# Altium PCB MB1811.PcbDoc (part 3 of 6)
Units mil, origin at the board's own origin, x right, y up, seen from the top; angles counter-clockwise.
Board outline 3480.3 x 4291.34 mil, 4 copper layers (Top Layer, L2_VCC, L3_GND, Bottom Layer), stack 30.59 mil thick; 371 components, 285 nets, 1369 pads, 606 vias.
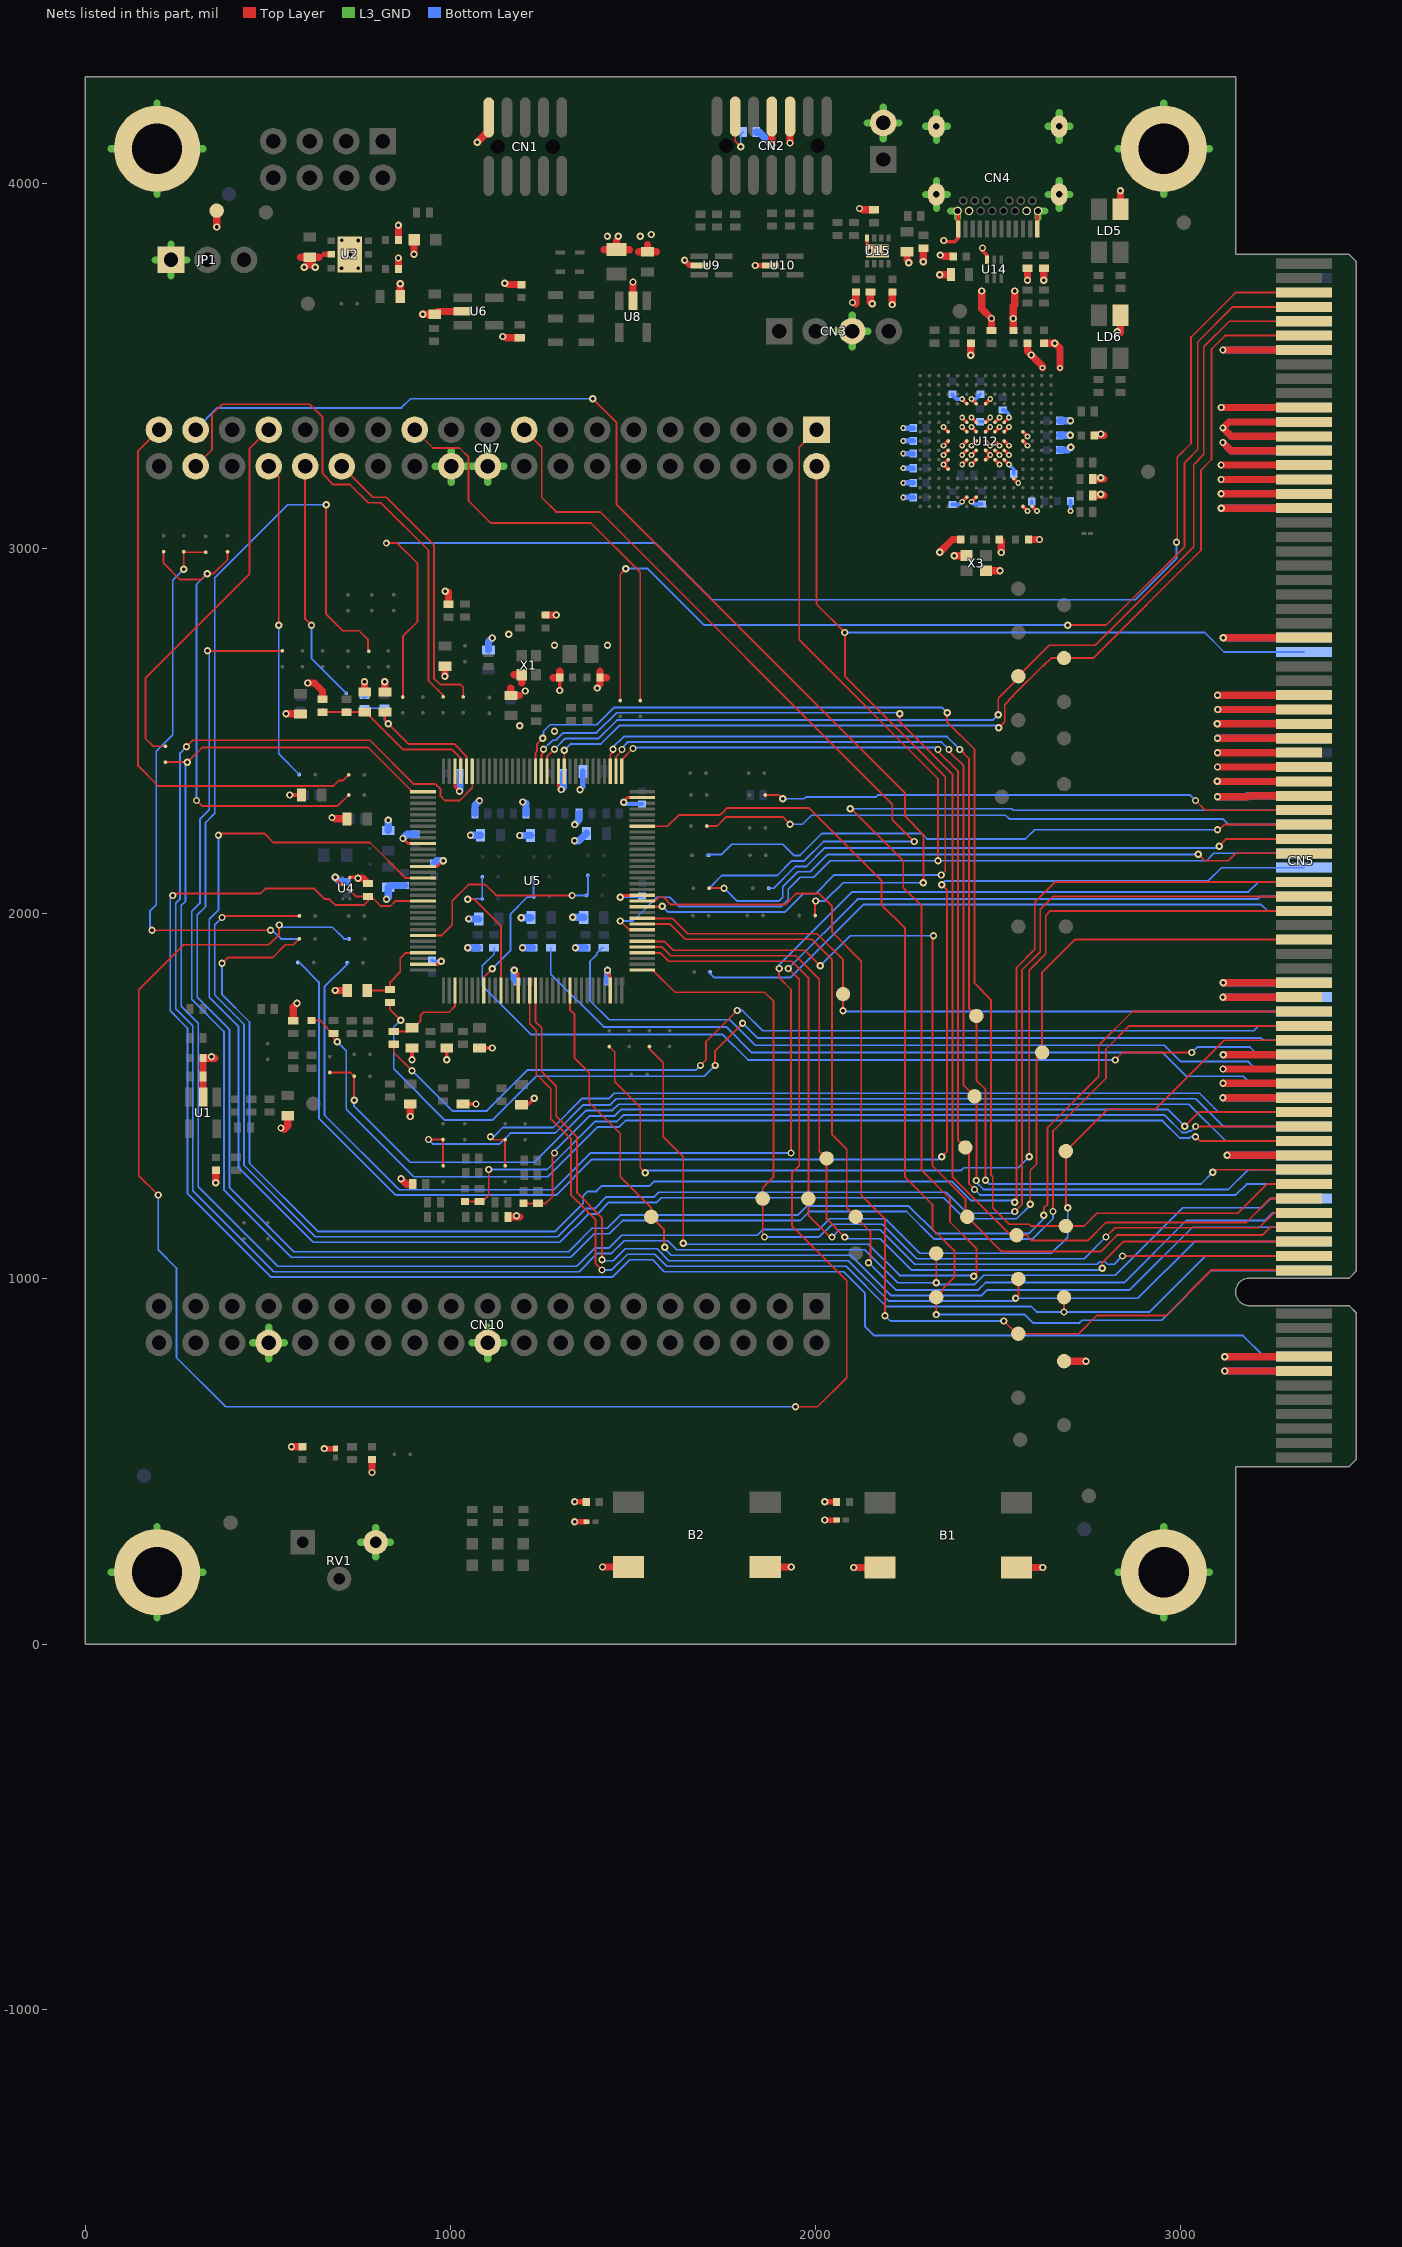
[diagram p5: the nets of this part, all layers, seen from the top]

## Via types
v1: diameter 20, hole 10, Top Layer to Bottom Layer, tented both sides, 524 vias
v2: diameter 16, hole 8, Top Layer to Bottom Layer, tented both sides, 82 vias

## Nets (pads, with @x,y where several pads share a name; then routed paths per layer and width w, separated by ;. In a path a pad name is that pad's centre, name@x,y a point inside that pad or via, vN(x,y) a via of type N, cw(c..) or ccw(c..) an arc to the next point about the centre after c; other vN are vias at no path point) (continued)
GND: B1.1 B1.2 B2.1 B2.2 C2.1 C3.1 C4.1 C5.1 C6.1 C8.1 C9.1 C10.1 C11.1 C12.1 C13.1 C14.1 C15.1 C16.1 C17.1 C18.1 C19.1 C20.1 C21.1 C23.1 C24.1 C25.1 C27.1 C28.1 C29.1 C30.1 C31.1 C32.1 C33.1 C34.2 C35.1 C36.2 C37.1 C38.1 C39.2 C40.2 C41.2 C42.2 C43.1 C44.1 C45.1 C46.1 C47.2 C48.1 C49.2 C50.2 C51.2 C52.2 C53.2 C54.2 C55.2 C56.2 C57.2 C58.2 C59.2 C60.2 C61.2 C62.1 C63.2 C64.1 C65.1 C66.1 C67.1 C68.1 C69.1 C70.1 C71.1 C72.1 C73.1 C74.1 C75.1 C76.1 C77.1 C78.1 C79.1 C80.1 C81.1 C82.1 C83.1 C84.1 C85.1 C86.1 C87.1 CN1.9 CN2.5 CN2.7 CN3.3 CN4.A1 CN4.A12 CN4.B1 CN4.B12 CN4.SH1 CN4.SH2 CN4.SH3 CN4.SH4 CN5.A07 CN5.A20 CN5.A24 CN5.A31 CN5.A32 CN5.A45 CN5.A49 CN5.A56 CN5.A65 CN5.A69 CN5.A76 CN5.B07 CN5.B08 CN5.B20 CN5.B24 CN5.B25 CN5.B26 CN5.B27 CN5.B31 CN5.B32 CN5.B45 CN5.B46 CN5.B47 CN5.B48 CN5.B49 CN5.B50 CN5.B51 CN5.B52 CN5.B56 CN5.B65 CN5.B66 CN5.B67 CN5.B68 CN5.B69 CN5.B70 CN5.B71 CN5.B72 CN5.B76 CN7.20 CN7.22 CN10.20 CN10.32 H1.1 H2.1 H3.1 H4.1 JP1.1 JP3.2 LD4.2 LD5.3 LD6.3 R4.1 R12.1 R34.1 R35.2 R48.2 R49.1 R51.2 R52.2 R56.2 R59.2 R78.1 R80.1 R82.1 R86.2 R87.1 R91.1 R92.1 R93.1 R94.1 R95.1 R96.1 R97.1 R98.1 R99.1 RV1.3 TP1.1 TP32.1 U1.2 U2.2 U2.EP U3.2 U4.2 U4.8 U5.12 U5.30 U5.42 U5.46 U5.63 U5.78 U5.94 U5.110 U5.127 U6.2 U7.2 U8.2 U9.2 U10.2 U11.2 U12.D5 U12.D6 U12.D7 U12.D8 U12.D9 U12.F2 U12.F6 U12.F7 U12.F8 U12.F9 U12.F10 U12.F12 U12.G2 U12.G6 U12.G7 U12.G8 U12.G9 U12.G10 U12.G12 U12.H6 U12.H7 U12.H8 U12.H9 U12.H10 U12.H12 U12.J6 U12.J7 U12.J8 U12.J9 U12.J10 U12.K6 U12.K7 U12.K8 U12.K9 U12.K10 U12.L4 U12.M1 U12.M8 U12.M9 U12.N1 U13.2 U14.3 U15.8 U15.9 X1.2 X3.2 X3.4 | length 19706.8
  Top Layer w8: v1(869.99,2206.04) 883.98,2192.05 U5.42@924.99,2192.05 ; U5.63@924.99,1861.34 966.32,1861.34 v1(974.99,1870.01) ; U5.46@924.99,2129.07 964.81,2129.06 v1(980.76,2145.01) ; U5.30@1012.39,2389.7 1012.39,2347.61 v1(1024.99,2335.01) ; v1(1174.99,1845.01) 1185.62,1834.38 U5.78@1185.62,1789.7 ; U5.12@1295.86,2389.7 1295.85,2349.15 1303.9,2341.1 v1(1303.9,2340.01) ; v1(1429.99,1845.01) 1429.99,1835.86 1437.59,1828.26 U5.94@1437.59,1789.7 ; v1(1464.99,2045.01) 1470.3,2050.32 U5.110@1524.99,2050.33 ; v1(1474.93,2304.76) v1(1474.93,2304.76) 1474.99,2308.03 1484.99,2318.03 U5.127@1524.99,2318.05
  Top Layer w9: v1(684.99,2100.01) 684.99,2095.01 700.15,2079.85 U4.2@705.15,2079.85 ; U15.9@2140.35,3824.22 U15.8@2140.35,3850.13
  Top Layer w10: v1(559.99,2325.01) C5.1@592.43,2325.01 ; U4.8@724.84,2099.54 744.48,2099.54 v1(746.86,2097.16) ; v1(894.99,1600.01) C16.1@894.99,1632.45 ; v1(989.99,1599.85) C20.1@989.99,1632.45 ; C21.1@1034.71,1479.14 v1(1069.99,1479.14) ; C23.1@1079.99,1632.45 v1(1114.99,1632.45) ; C25.1@1194.83,1476.97 1211.95,1476.97 v1(1229.99,1495.01) ; v1(1299,2611) C29.1@1299,2646.29 ; v1(1401.87,2617.7) 1409.44,2625.27 C31.1@1409.44,2646.29 ; U15.9@2140.35,3824.22 v1(2149.87,3814.7) ; v2(2350.02,3255.73) U12.D7@2362.81,3268.52 ; v2@2350.02,3281.33 U12.D8@2362.81,3294.12 ; v2@2350.02,3332.5 U12.D9@2362.81,3319.71 ; v1@2359.87,3839.7 2380.46,3839.7 2390.46,3849.7 2390.46,3922.03 CN4.B1@2388.49,3924 ; U12.D5@2362.81,3217.34 v2(2350.01,3230.14) U12.D6@2362.81,3242.93 ; v2(2401.19,3332.5) U12.F9@2413.99,3319.71 ; v2(2401.19,3358.09) U12.F10@2413.99,3345.3 ; v2(2401.19,3409.27) U12.F12@2413.99,3396.48 ; v2(2401.2,3127.78) U12.F2@2413.99,3140.57 ; v2(2401.2,3230.14) U12.F6@2413.99,3242.93 ; v2(2401.2,3255.73) U12.F7@2413.99,3268.52 ; v2(2401.2,3281.33) U12.F8@2413.99,3294.12 ; v2(2426.79,3127.78) U12.G2@2439.58,3140.57 ; v2(2426.79,3230.14) U12.G6@2439.58,3242.93 ; v2(2426.79,3255.73) U12.G7@2439.58,3268.52 ; v2(2426.79,3281.33) U12.G8@2439.58,3294.12 ; v2(2426.78,3332.5) U12.G9@2439.58,3319.71 ; v2(2426.78,3358.09) U12.G10@2439.58,3345.3 ; v2(2426.78,3409.27) U12.G12@2439.58,3396.48 ; v1(2456.77,3822.7) 2456.77,3815.4 2469.18,3802.99 U14.3@2469.18,3790.29 ; U12.H6@2465.18,3242.93 v2(2477.97,3255.74) U12.H7@2465.18,3268.52 ; U12.H8@2465.18,3294.12 v2(2477.97,3281.33) ; U12.H9@2465.18,3319.71 v2(2477.96,3332.5) ; U12.H10@2465.18,3345.3 v2(2477.96,3358.1) ; U12.H12@2465.18,3396.48 v2(2477.96,3409.27) ; U12.J6@2490.77,3242.93 v2(2503.56,3230.15) ; U12.J7@2490.77,3268.52 v2(2503.55,3255.74) ; U12.J8@2490.77,3294.12 v2(2503.56,3281.33) ; U12.J9@2490.77,3319.71 v2(2503.55,3332.5) ; U12.J10@2490.77,3345.3 v2(2503.55,3358.09) ; U12.K6@2516.36,3242.93 v2(2529.15,3230.15) ; U12.K7@2516.36,3268.52 v2(2529.14,3255.74) ; U12.K8@2516.36,3294.12 v2(2529.14,3281.33) ; U12.K9@2516.36,3319.71 v2(2529.14,3332.5) ; U12.K10@2516.36,3345.3 v2(2529.14,3358.09) ; U12.L4@2541.94,3191.75 v2(2554.73,3178.96) ; U12.M9@2567.54,3319.71 v2(2580.32,3306.92) ; U12.M1@2567.54,3114.98 v2(2580.33,3102.19) ; U12.M8@2567.54,3294.12 v2(2580.33,3281.33) ; U12.N1@2593.13,3114.98 v2(2605.92,3102.19) ; CN4.A1@2607,3874.79 2607,3922.04 CN4.B12@2608.97,3924
  Top Layer w15: v1(654.87,535.62) U3.2@685.27,535.62 ; 654.99,3805.01 U2.2@673.81,3805.01 ; v1(1340,335) U7.2@1372.69,335 ; v1(1340,390) C30.1@1372.27,390 ; v1(1641.17,3788.79) 1643.37,3786.59 1643.37,3786.2 1654.87,3774.7 U9.2@1681.4,3774.7 ; v1(1834.7,3774.7) U10.2@1876.4,3774.7 ; v1(2025,340) U11.2@2057.69,340 ; v1(2025,390) C37.1@2057.27,390
  Top Layer w20: U1.2@322.88,1498.29 322.46,1498.7 322.46,1554.58 R4.1@322.59,1554.7 C86.1@322.59,1604.7 v1@354.87,1604.7 ; v1(357.87,1263.7) C2.1@357.87,1297.27 ; v1(359.99,3880.01) TP1.1@359.99,3925 ; v1@544.87,1409.7 554.87,1419.7 C3.1@554.87,1447.13 ; v1(549.88,2547.14) C24.1@589.87,2547.14 ; v1(564.87,541.04) C6.1@595.27,541.04 ; R78.1@569.87,1707.42 569.87,1744.7 v1(579.87,1754.7) ; 590.45,3797.45 C8.1@614.99,3797.45 ; v1(599.99,3769.85) 614.99,3777.83 ; v1(609.87,2631.68) 627.89,2631.68 649.87,2609.7 R95.1@649.87,2587.42 ; v1(629.99,3769.85) 614.99,3777.83 ; 639.53,3797.45 C8.1@614.99,3797.45 ; v1@684.87,2259.7 C76.1@717.31,2259.7 ; v1(684.99,1790.01) C9.1@717.42,1790.01 ; v1(746.86,2097.16) 760.55,2097.16 R12.1@774.99,2082.72 ; v1(764.87,2634.7) 764.87,2608.04 C10.1@765.66,2607.25 ; v1(785.27,470.29) C11.1@785.27,505.6 ; C13.1@820.66,2607.24 v1(820.66,2635.01) ; C14.1@857.71,3765.01 v1(857.71,3795.01) ; C15.1@857.71,3845.01 v1(857.71,3885.01) ; C12.1@862.55,3690.01 v1(862.55,3725.01) ; v1(864.87,1274.7) 879.87,1259.7 R80.1@897.16,1259.7 ; v1(890,1445.02) C17.1@890,1478.67 ; v1(900.46,3805.48) LD4.2@900.47,3845.01 ; v1(924.59,3641.38) C18.1@957.11,3641.38 964.67,3648.94 U6.2@1033.81,3648.94 ; v1(984.99,2650.03) C19.1@984.99,2677.45 ; R96.1@994.87,2847.42 v1@994.87,2879.7 ; v1(1073.49,4112.11) 1104.99,4143.61 CN1.9@1104.99,4180.12 ; v1@1152.59,3576.98 R34.1@1189.87,3576.98 ; R82.1@1157.59,1169.7 v1@1189.87,1169.7 ; v1@1157.58,3722.41 C27.1@1194.87,3722.41 ; 1164.87,2616.88 1164.87,2597.26 1189.41,2597.26 ; 1174.5,2654.41 X1.2@1195.3,2654.41 1195.3,2631.64 ; C28.1@1259.99,2817.72 v1(1289.99,2817.72) ; 1281.94,2646.29 C29.1@1299,2646.29 1299,2664.34 ; 1409.43,2628.24 C31.1@1409.44,2646.29 ; v1(1416.4,211.42) B2.2@1487.99,211.42 ; 1420.29,3818.16 C32.1@1454.87,3818.16 ; 1426.5,2646.29 C31.1@1409.44,2646.29 ; 1454.87,3842.9 C32.1@1454.87,3818.16 ; 1489.45,3818.16 C32.1@1454.87,3818.16 ; U8.2@1499.88,3678.01 v1(1499.87,3729.7) ; 1515.33,3812.26 C35.1@1539.87,3812.26 ; 1539.87,3831.88 C35.1@1539.87,3812.26 ; 1564.41,3812.26 C35.1@1539.87,3812.26 ; B2.1@1862,211.42 v1(1933.58,211.42) ; v1(1879.99,4105.01) CN2.7@1879.99,4182.6 ; v1(1929.99,4110.01) CN2.5@1929.99,4182.6 ; v1(2104.39,210) B1.2@2175.98,210 ; v1@2109.87,3669.7 C87.1@2109.87,3701.98 ; v1@2129.09,3927.42 R86.2@2159.87,3927.42 ; R87.1@2149.87,3701.98 2149.87,3674.7 v1(2154.87,3669.7) ; v1(2209.87,3667.7) C46.1@2209.87,3701.99 ; C45.1@2249.87,3812.14 2249.87,3789.7 2254.87,3784.7 v1(2254.87,3782.54) ; v1(2294.87,3784.7) R59.2@2294.87,3821.99 ; v1(2339.87,2989.7) 2374.87,3024.7 C39.2@2397.15,3024.7 ; v1(2339.87,3749.7) U13.2@2370.27,3749.7 ; v1@2349.87,3799.7 C42.2@2377.16,3799.7 ; v1(2379.2,2980.37) X3.4@2413.29,2980.37 ; v1(2424.87,3529.13) C33.1@2424.87,3561.99 ; v1(2454.87,3704.7) 2454.87,3656.18 v1(2481.35,3629.7) R48.2@2481.35,3596.84 ; X3.2@2466.44,2939.03 v1(2504.87,2939.03) ; C44.1@2502.59,3024.7 2507.77,3019.51 v1(2507.77,2989) ; C38.1@2541.35,3596.84 v1(2541.35,3629.7) 2541.35,3664 2544.87,3667.52 v1(2544.87,3704.7) ; B1.1@2549.99,210 v1(2621.57,210) ; C34.2@2579.87,3561.98 2579.87,3539.7 v1(2589.87,3529.7) 2620.82,3498.75 v2(2620.82,3494.7) ; v1(2579.87,3734.7) R35.2@2579.87,3766.98 ; C48.1@2582.59,3024.7 v1(2613.07,3024.7) ; C36.2@2624.87,3561.99 v1(2654.87,3561.99) 2669,3547.86 v2(2669,3494) ; v1(2624.87,3734.7) R56.2@2624.87,3766.98 ; TP32.1@2679.99,775 v1(2739.98,775) ; R52.2@2759.07,3145.3 v1@2789.27,3145.3 ; R51.2@2759.07,3190.3 v1@2789.27,3190.3 ; C43.1@2762.59,3309.7 v1@2789.62,3309.7 ; v1@2834.4,3590.17 LD6.3@2834.41,3638.75 ; LD5.3@2834.41,3928.76 v1(2834.4,3979.7) ; v1(3099.67,2519.69) CN5.B50@3336.8,2519.7 ; v1(3099.91,2362.51) 3100.21,2362.21 CN5.B46@3336.8,2362.22 ; v1(3099.99,2320.01) 3184.99,2320.01 3187.82,2322.84 CN5.B45@3336.8,2322.85 ; v1(3099.99,2401.58) CN5.B47@3336.8,2401.59 ; v1(3099.99,2440.95) CN5.B48@3322.82,2440.95 ; v1(3099.99,2480.32) CN5.B49@3336.8,2480.33 ; v1(3099.99,2598.43) CN5.B52@3336.8,2598.44 ; v1(3100.94,2559.06) CN5.B51@3336.8,2559.07 ; v1(3109.99,3149.61) CN5.B66@3336.8,3149.62 ; v1(3109.99,3188.98) CN5.B67@3336.8,3188.99 ; v1(3109.99,3228.35) CN5.B68@3336.8,3228.35 ; v1(3110.22,3110.24) CN5.B65@3336.8,3110.25 ; v1(3110.81,3385.83) CN5.B72@3336.8,3385.84 ; v1(3114.99,1496.07) CN5.B24@3336.8,1496.07 ; v1(3114.99,1771.66) CN5.B31@3322.83,1771.66 ; v1(3114.99,3290.01) 3137.28,3267.72 CN5.B69@3336.8,3267.73 ; v1(3114.99,3543.31) CN5.B76@3336.8,3543.32 ; v1(3115.19,1574.81) CN5.B26@3336.8,1574.81 ; v1(3115.42,1535.44) CN5.B25@3336.8,1535.44 ; v1(3115.82,1614.18) CN5.B27@3336.8,1614.18 ; v1(3115.89,2755.91) CN5.B56@3336.8,2755.92 ; v1(3116.01,1811.03) CN5.B32@3336.8,1811.03 ; v1(3119.99,748.04) CN5.B07@3336.8,748.04 ; v1(3119.99,787.41) CN5.B08@3336.8,787.41 ; v1(3126.41,1338.59) CN5.B20@3336.8,1338.59 ; CN5.B70@3336.8,3307.1 3137.91,3307.09 v1(3114.99,3330.01) 3131.44,3346.46 CN5.B71@3336.8,3346.47 ; 614.99,3777.83 C8.1@614.99,3797.45 ; C31.1@1409.44,2646.29 1409.44,2664.34 C31.1@1409.44,2646.29
  L3_GND w20: 71.7,196.87 H3.1@196.84,196.86 ; 71.7,4094.5 H4.1@196.84,4094.49 ; 191.54,3790.01 JP1.1@234.99,3790 ; 196.83,71.74 H3.1@196.84,196.86 ; 196.83,322 H3.1@196.84,196.86 ; 196.83,3969.37 H4.1@196.84,4094.49 ; 196.83,4219.63 H4.1@196.84,4094.49 ; 234.98,3746.57 JP1.1@234.99,3790 ; 234.98,3833.45 JP1.1@234.99,3790 ; 278.42,3790.01 JP1.1@234.99,3790 ; 321.96,196.87 H3.1@196.84,196.86 ; 321.96,4094.5 H4.1@196.84,4094.49 ; 458.92,825.01 CN10.32@502.37,825 ; 502.36,781.57 CN10.32@502.37,825 ; 502.36,868.45 CN10.32@502.37,825 ; 545.8,825.01 CN10.32@502.37,825 ; 754.77,279.12 RV1.3@795.27,279.11 ; 795.26,238.63 RV1.3@795.27,279.11 ; 795.26,319.61 RV1.3@795.27,279.11 ; 835.75,279.12 RV1.3@795.27,279.11 ; 958.92,3225.01 CN7.22@1002.37,3225 ; 1002.36,3181.57 CN7.22@1002.37,3225 ; 1002.36,3268.45 CN7.22@1002.37,3225 ; 1045.8,3225.01 CN7.22@1002.37,3225 ; 1058.92,825.01 CN10.20@1102.37,825 ; 1058.92,3225.01 CN7.20@1102.37,3225 ; 1102.36,781.57 CN10.20@1102.37,825 ; 1102.36,868.45 CN10.20@1102.37,825 ; 1102.36,3181.57 CN7.20@1102.37,3225 ; 1102.36,3268.45 CN7.20@1102.37,3225 ; 1145.8,825.01 CN10.20@1102.37,825 ; 1145.8,3225.01 CN7.20@1102.37,3225 ; 2056.54,3595.01 CN3.3@2099.99,3595 ; 2099.98,3551.57 CN3.3@2099.99,3595 ; 2099.98,3638.45 CN3.3@2099.99,3595 ; 2141.54,4165.02 JP3.2@2184.99,4165.01 ; 2143.42,3595.01 CN3.3@2099.99,3595 ; 2184.98,4121.58 JP3.2@2184.99,4165.01 ; 2184.98,4208.46 JP3.2@2184.99,4165.01 ; 2228.42,4165.02 JP3.2@2184.99,4165.01 ; 2300.95,3969.29 CN4.SH3@2330.61,3969.29 ; 2300.95,4155.51 CN4.SH4@2330.61,4155.51 ; 2330.61,3931.76 CN4.SH3@2330.61,3969.29 ; 2330.61,4006.82 CN4.SH3@2330.61,3969.29 ; 2330.61,4117.98 CN4.SH4@2330.61,4155.51 ; 2330.61,4193.04 CN4.SH4@2330.61,4155.51 ; 2360.27,3969.29 CN4.SH3@2330.61,3969.29 ; 2360.27,4155.51 CN4.SH4@2330.61,4155.51 ; 2369.65,3924.02 CN4.B1@2388.49,3924 2388.48,3905.19 ; 2608.95,3905.19 CN4.B12@2608.97,3924 2627.78,3924.02 ; 2637.17,3969.29 CN4.SH1@2666.84,3969.28 ; 2637.17,4155.51 CN4.SH2@2666.84,4155.5 ; 2666.83,3931.76 CN4.SH1@2666.84,3969.28 ; 2666.83,4006.82 CN4.SH1@2666.84,3969.28 ; 2666.83,4117.98 CN4.SH2@2666.84,4155.5 ; 2666.83,4193.04 CN4.SH2@2666.84,4155.5 ; 2696.49,3969.29 CN4.SH1@2666.84,3969.28 ; 2696.49,4155.51 CN4.SH2@2666.84,4155.5 ; 2827.6,196.87 H1.1@2952.74,196.86 ; 2827.6,4094.5 H2.1@2952.74,4094.49 ; 2952.73,71.74 H1.1@2952.74,196.86 ; 2952.73,322 H1.1@2952.74,196.86 ; 2952.73,3969.37 H2.1@2952.74,4094.49 ; 2952.73,4219.63 H2.1@2952.74,4094.49 ; 3077.86,196.87 H1.1@2952.74,196.86 ; 3077.86,4094.5 H2.1@2952.74,4094.49
  Bottom Layer w10: C79.1@949.99,1872.73 952.71,1870.01 v1(974.99,1870.01) ; v1(1464.99,2045.01) 1468.33,2048.35 C64.1@1524.99,2048.35 ; v1(1474.93,2304.76) 1479.37,2300.32 C65.1@1524.99,2300.32 ; C50.2@2374.7,3120.4 2375.7,3121.4 2379.7,3121.4 2394.82,3121.4 v2(2401.2,3127.78) ; C62.1@2374.87,3421.99 2374.87,3419.27 2384.87,3409.27 v2(2401.19,3409.27) ; v2(2426.79,3127.78) 2432.69,3121.88 C51.2@2455.18,3121.88 ; v2(2426.78,3409.27) 2438.16,3409.27 C40.2@2450.87,3421.98 ; C63.2@2449.87,3346.98 2466.84,3346.98 v2(2477.96,3358.1) ; C41.2@2512.27,3378.88 2517.97,3378.88 2529.14,3367.71 v2(2529.14,3358.09) ; v2(2529.15,3230.15) 2542.42,3216.86 C54.2@2542.42,3204.12 ; v2(2529.15,3230.15) 2542.42,3216.88 ; v2@2554.73,3176.85 v2(2554.73,3178.96) ; C52.2@2591.99,3129.12 2591.98,3116.12 v2@2605.91,3102.19
  Bottom Layer w12: v2(2697.59,3102.42) C47.2@2697.6,3129.7
  Bottom Layer w15: v1(1354.99,2339.65) 1354.99,2340.01 1362.78,2347.8 C69.1@1362.78,2389.69 ; v2(2239.87,3139.7) C49.2@2267.16,3139.7 ; v2(2239.87,3179.58) C53.2@2267.48,3179.58 ; v2(2239.87,3219.58) C55.2@2267.48,3219.58 ; v2(2239.87,3259.58) C56.2@2267.48,3259.58 ; v2(2239.87,3294.58) C58.2@2267.48,3294.58 ; v2(2239.87,3329.7) C60.2@2267.16,3329.7
  Bottom Layer w20: v1(684.99,2100.01) 697.28,2087.72 C85.1@714.99,2087.72 ; R94.1@764.87,2597.42 v1(764.87,2634.7) ; v1(824.99,2040.01) 829.99,2045.01 829.99,2072.45 834.84,2077.3 C82.1@874.99,2077.3 ; v1(829.72,2256.36) 829.72,2227.84 C84.1@829.99,2227.57 ; v1(869.99,2206.04) 881.67,2217.72 C81.1@904.99,2217.72 ; C78.1@954.99,2137.73 962.27,2145.01 v1(980.76,2145.01) ; v1(1024.99,2335.01) 1026.17,2336.19 C77.1@1026.18,2384.69 ; v1(1047.27,1906.97) R93.1@1074.87,1906.98 ; v1@1049.84,1985.76 C75.1@1077.43,1985.76 ; v1(1054.87,2215.01) C74.1@1082.43,2215.01 ; R99.1@1067.16,2274.7 1067.15,2296.98 v1(1079.87,2309.7) ; C4.1@1104.56,2722.14 1104.56,2744.39 v1(1114.87,2754.7) ; v1(1174.99,1845.01) 1174.99,1822.29 C73.1@1182.27,1815.01 ; v1(1189.87,2214.11) C72.1@1219.68,2214.11 ; v1(1194.25,1989.27) C71.1@1220.89,1989.28 ; v1(1197.27,1906.97) R91.1@1224.87,1906.98 ; R97.1@1207.16,2274.7 v1@1207.15,2302.42 ; v1(1303.9,2340.01) 1309.63,2345.74 C70.1@1309.64,2384.69 ; v1(1334.98,1990) C68.1@1364.99,1990 ; v1(1339.87,2199.7) 1352.13,2199.7 C67.1@1372.43,2220 ; v1(1340.19,2244.02) 1340.19,2244.38 1352.15,2256.34 R98.1@1352.16,2274.7 ; v1(1342.27,1906.97) R92.1@1369.87,1906.98 ; v1(1429.99,1845.01) 1429.99,1817.3 C66.1@1432.28,1815.01 ; R49.1@1837.59,4139.7 1845.3,4139.7 v1(1879.99,4105.01) ; C57.2@2667.9,3269.58 2690.75,3269.58 v1(2698.37,3277.2) ; C59.2@2667.9,3309.58 v1(2697.11,3309.58) ; C61.2@2667.9,3349.58 v1(2697.93,3349.58) ; v1(3099.99,2320.01) 3179.99,2320.01 3182.82,2322.84 CN5.A45@3336.8,2322.85 ; v1(3099.99,2480.32) CN5.A49@3336.8,2480.33 ; v1(3110.22,3110.24) CN5.A65@3336.8,3110.25 ; v1(3114.99,1496.07) CN5.A24@3336.8,1496.07 ; v1(3114.99,1771.66) CN5.A31@3336.8,1771.66 ; v1(3114.99,3290.01) 3137.28,3267.72 CN5.A69@3336.8,3267.73 ; v1(3114.99,3543.31) CN5.A76@3336.8,3543.32 ; v1(3115.89,2755.91) CN5.A56@3336.8,2755.92 ; v1(3116.01,1811.03) CN5.A32@3336.8,1811.03 ; v1(3119.99,748.04) CN5.A07@3336.8,748.04 ; v1(3126.41,1338.59) CN5.A20@3336.8,1338.59
  other v1: 1181.03,1173.21 536.03,1413.21 346.03,1608.21 1049.83,1985.75 676.03,2263.21 1198.31,2305.93 1284.87,2499.7 1189.87,2514.45 1204.87,2609.7 1284.99,2735.01 1429.99,2735.01 1159.99,2765.01 986.03,2883.21 2780.43,3148.81 2780.43,3193.81 2780.78,3313.21 1143.75,3580.49 2825.56,3593.68 2101.03,3673.21 1148.74,3725.92 701.99,3767.01 747.99,3767.01 2341.03,3803.21 724.99,3805.01 2189.87,3814.7 747.99,3843.01 702.99,3844.01 2351.03,3843.21 1429.87,3854.7 1459.87,3854.7 1519.87,3854.7 1549.87,3859.7 2120.25,3930.93
  other v2: 2350.01,3281.33 2350.01,3332.5
GNDDetect: CN2.11 R49.2 | length 132.7
  Top Layer w5: CN2.11@1779.99,4182.6 1779.99,4115.01 v1(1794.99,4100.01)
  Bottom Layer w5: v1(1794.99,4100.01) 1794.99,4134.7 1799.99,4139.7 R49.2@1802.15,4139.7
ID_Enable: CN5.A08 R12.2 U4.6 U5.52 | length 4972.5
  Top Layer w5: v1(239.87,2049.7) 245.87,2055.7 480.87,2055.7 493.87,2068.7 627.86,2068.7 656.55,2040.01 668.56,2040.01 679.49,2029.08 685.44,2023.98 763.96,2023.98 774.99,2035.01 R12.2@774.99,2047.29 ; U4.6@724.84,2060.17 728.48,2060.17 741.36,2047.29 R12.2@774.99,2047.29 ; U5.52@924.99,2034.58 849.54,2034.57 836.07,2021.1 808.9,2021.1 782.71,2047.29 R12.2@774.99,2047.29
  Bottom Layer w5: v1(239.87,2049.7) 232.99,2042.82 232.99,1734.02 279.87,1687.14 279.87,1235.13 509.99,1005.01 1443.52,1005.01 1491.05,1052.51 1553.46,1052.51 1585.96,1020.01 2077.01,1020.01 2134.99,962.03 2134.99,870.01 2159.99,845.01 3169.99,845.01 3227.59,787.41 CN5.A08@3336.8,787.41
Inrush_lim.: CN5.B35 TP30.1 U5.48 | length 5313.3
  Top Layer w5: v1(364.87,2214.7) 370.18,2220.01 489.98,2220.01 514.98,2195.01 779.99,2195.01 877.44,2097.56 U5.48@924.99,2097.57 ; v1(2587.37,1204.7) 2587.37,1297.2 2604.87,1314.7 2604.87,1604.89 TP30.1@2619.99,1620.01 2619.99,1839.81 2709.32,1929.14 CN5.B35@3336.8,1929.14
  Bottom Layer w5: v1(364.87,2214.7) 364.87,2009.7 339.87,1984.7 339.87,1771.25 419.99,1691.13 419.99,1304.7 624.28,1100.41 1299.79,1100.41 1377.08,1177.7 1401.52,1177.7 1433.52,1209.7 1564.5,1209.7 1577,1222.2 2351.16,1222.2 2408.66,1164.7 2549.88,1164.7 2587.37,1202.19 v1(2587.37,1204.7)
L1_PG6: CN5.A41 CN7.1 U5.104 | length 3413.2
  Top Layer w5: v1(1464.99,1980.01) 1489.17,1955.83 U5.104@1524.99,1955.84 ; CN7.1@2002.37,3325 1954.99,3277.62 1954.99,2750.01 2334.87,2370.13 v1(2334.87,2145.01)
  Bottom Layer w5: v1(1464.99,1980.01) 1499.99,1980.01 1564.99,2045.01 1599.99,2045.01 1624.99,2020.01 1906.4,2020.01 1924.87,2038.48 1924.87,2067.25 1957.32,2099.7 1994.87,2099.7 2040.18,2145.01 v1(2334.87,2145.01) 3069.99,2145.01 3090.34,2165.36 CN5.A41@3336.8,2165.36
L2_PD0: CN5.A55 CN7.2 U5.108 | length 3416.1
  Top Layer w5: U5.108@1524.99,2018.83 1563.8,2018.82 1564.55,2019.57 1578.99,2019.57 v1(1579.99,2020.57) ; CN7.2@2002.37,3225 2002.35,2847.66 v1(2079.99,2770.01) 2079.99,2650.01 2354.87,2375.13 2354.87,2117.51 v1(2343.47,2106.11)
  Bottom Layer w5: v1(1579.99,2020.57) 1595.55,2005.01 1916.21,2005.01 1965.9,2054.7 1999.86,2054.7 2051.27,2106.11 v1(2343.47,2106.11) ; v1(2079.99,2770.01) 3064.55,2770.01 3118.02,2716.54 CN5.A55@3336.8,2716.55
L17_PD3: CN7.17 SB70.2 | length 2254
  Top Layer w5: CN7.17@1202.37,3325 1249.99,3277.38 1249.99,3139.57 1289.55,3100.01 1409.57,3100.01 2209.87,2299.71 2209.87,2257.51 v1(2269.87,2197.51)
  Bottom Layer w5: SB70.2@1708.61,2070.01 1743.3,2104.7 1894.68,2104.7 1934.68,2144.7 1968.65,2144.7 2021.46,2197.51 v1(2269.87,2197.51)
L23_PE5: CN7.23 SB44.2 | length 1200.6
  Top Layer w5: CN7.23@902.37,3325 952.36,3275.01 1024.99,3275.01 1049.99,3250.01 1049.99,3130.01 1110.3,3069.7 1384.86,3069.7 1519.99,2934.57 SB44.2@1519.99,2583.63
L28_PC2: CN7.28 SB34.2 | length 823.4
  Top Layer w5: CN7.28@702.37,3225 787.36,3140.01 824.56,3140.01 954.99,3009.58 954.99,2644.57 972.05,2627.51 1027.49,2627.51 1034.99,2620.01 SB34.2@1034.99,2593.64
L30_PA3: CN7.30 SB82.2 | length 668.3
  Top Layer w5: CN7.30@602.37,3225 602.37,2807.2 v1(619.87,2789.7)
  Bottom Layer w5: v1(619.87,2789.7) 619.87,2698.32 SB82.2@714.87,2603.32
L31_PA4: CN7.31 SB61.2 | length 1049
  Top Layer w5: SB61.2@219.87,2458.32 186.25,2458.32 164.87,2479.7 164.87,2644.7 449.87,2929.7 449.87,3272.5 CN7.31@502.37,3325
L32_PA5: CN7.32 SB91.2 | length 878.7
  Top Layer w5: CN7.32@502.37,3225 529.87,3197.5 v1(529.87,2789.7)
  Bottom Layer w5: v1(529.87,2789.7) 529.87,2437.55 SB91.2@586.37,2381.06
L34_PE10: SB62.2 SB64.2 SB90.2 | length 1551.4
  Top Layer w5: v1(182.99,1954.7) 507.18,1954.7 v1(507.49,1955.01) ; v1(270,2943) 269.87,2943.13 SB64.2@269.87,2991.15 271.32,2989.69 SB62.2@330,2989.69
  Bottom Layer w5: v1(182.99,1954.7) 182.99,1956.58 177.37,1962.2 177.37,2007.2 194.87,2024.7 194.87,2444.7 239.87,2489.7 239.87,2912.87 v1(270,2943) ; v1(507.49,1955.01) 512.49,1955.01 536.43,1931.07 SB90.2@586.37,1931.07
L35_PA9: CN7.35 SB60.2 | length 3178.5
  Top Layer w5: v1(1389.87,3409.7) 1454.87,3344.7 1454.87,3119.7 2244.87,2329.7 2244.87,2266.69 2294.99,2216.57 v1(2294.99,2085.01) ; SB60.2@1998.61,1995.01 1998.61,2033.63 v1(1999.99,2035.01)
  Bottom Layer w5: CN7.35@302.37,3325 362.07,3384.7 865.87,3384.7 890.87,3409.7 v1(1389.87,3409.7) ; v1(1999.99,2035.01) 2025.19,2035.01 2075.19,2085.01 v1(2294.99,2085.01)
L36_PC3: CN7.36 SB30.2 | length 1441.4
  Top Layer w5: CN7.36@302.37,3225 347.38,3270.01 347.38,3367.21 374.87,3394.7 614.87,3394.7 649.99,3359.58 649.99,3204.57 679.86,3174.7 725.18,3174.7 774.87,3125.01 809.56,3125.01 939.99,2994.58 939.99,2638.35 965.83,2612.51 ; 967.07,2612.51 965.83,2612.51 ; SB30.2@980,2593.62 SB30.2@979.99,2598.35 ; 979.99,2599.59 SB30.2@979.99,2598.35 ; 965.83,2612.51 SB30.2@979.99,2598.35
L37_PA7: CN7.37 SB17.2 | length 1555.7
  Top Layer w5: CN7.37@202.37,3325 144.87,3267.5 144.87,2404.69 199.55,2350.01 576.7,2350.01 ; 576.72,2350.03 663.26,2350.03 ; 663.28,2350.01 679.99,2350.01 694.99,2365.01 706.37,2365.01 SB17.2@721.38,2380.01
L38_PC4: SB15.2 SB63.2 SB65.2 | length 1337.3
  Top Layer w5: SB65.2@214.87,2991.16 214.87,2959.7 259.57,2915 318,2915 v1(334,2931) 351.17,2931 389.87,2969.7 SB63.2@389.87,2991.16 ; v1(304.87,2310.01) 319.87,2295.01 691.37,2295.01 SB15.2@721.37,2325.01
  Bottom Layer w5: v1(304.87,2310.01) 304.87,2901.87 v1(334,2931)
M1_DissipativeBrake: CN5.A30 TP9.1 U5.106 | length 1998.9
  Top Layer w5: U5.106@1524.99,1987.34 1525.48,1986.83 1607.85,1986.83 1611.1,1983.58 1611.18,1983.58 1649.75,1945.01 2003.77,1945.01 2074.99,1873.79 TP9.1@2074.99,1780.01 v1(2074.99,1734.7)
  Bottom Layer w5: v1(2074.99,1734.7) 2077.39,1732.3 CN5.A30@3336.8,1732.29
M1_Emergency(BKIN2): CN5.B12 TP21.1 U5.109 | length 2980.4
  Top Layer w5: U5.109@1524.99,2034.58 1559.55,2034.57 1569.99,2045.01 1583.77,2045.01 1603.77,2025.01 1916.21,2025.01 1946.21,2055.01 2009.99,2055.01 2044.99,2020.01 2044.99,1950.01 2124.99,1870.01 2124.99,1229.02 2189.99,1164.02 v1(2189.99,899.7) ; v1(2514.99,885.01) 2550,850 TP21.1@2554.99,850 2719.98,850 2769.99,900.01 2960,900.01 3084.99,1025 3335.43,1025 CN5.B12@3336.8,1023.63
  Bottom Layer w5: v1(2189.99,899.7) 2204.68,885.01 v1(2514.99,885.01)
M1_Emergency(BKIN): CN5.A12 TP12.1 U5.122 | length 3126.3
  Top Layer w5: U5.122@1524.99,2239.31 1594.27,2239.29 1624.99,2270.01 1737.43,2270.01 1742.43,2275.01 1743.77,2275.01 1758.46,2289.7 1981.52,2289.7 2179.99,2091.23 2179.99,2025.01 2244.99,1960.01 2244.99,1278.78 2319.99,1203.78 2319.99,1137.57 2379.99,1077.57 2379.99,1005 2349.23,974.24 2349.23,969.25 TP12.1@2329.99,950.01 v1(2329.99,902.51)
  Bottom Layer w5: v1(2329.99,902.51) 2572.06,902.51 2594.87,879.7 2722.07,879.7 2729.57,887.2 2947.18,887.2 3083.61,1023.63 CN5.A12@3336.8,1023.63
M1_Enable1: CN5.B77 TP37.1 U5.11 | length 2892.7
  Top Layer w5: U5.11@1311.6,2389.7 v1(1311.6,2447.51) ; v1(2501.24,2508.76) 2517.49,2525.01 2517.49,2572.51 2539.99,2595.01 2539.99,2596.23 2623.77,2680.01 2624.99,2680.01 2644.99,2700.01 TP37.1@2679.99,2700.01 2759.99,2700.01 3054.99,2995.01 3054.99,3214.7 3083.77,3243.48 3083.77,3545.79 3120.66,3582.68 CN5.B77@3336.8,3582.69
  Bottom Layer w5: v1(1311.6,2447.51) 1329.1,2465.01 1412.31,2465.01 1462.31,2515.01 2494.99,2515.01 v1(2501.24,2508.76)
M1_Enable2: CN5.B78 TP26.1 U5.14 | length 2939.5
  Top Layer w5: U5.14@1264.36,2389.7 1264.36,2429.38 v1(1284.99,2450.01) ; v1(2499.99,2545.01) 2499.99,2590.01 2554.99,2645.01 TP26.1@2554.99,2650.01 2639.99,2735.01 2764.99,2735.01 3034.99,3005.01 3034.99,3229.7 3062.77,3257.48 3062.77,3551.79 3133.03,3622.05 CN5.B78@3336.8,3622.05
  Bottom Layer w5: v1(1284.99,2450.01) 1314.99,2480.01 1406.09,2480.01 1456.09,2530.01 2484.99,2530.01 v1(2499.99,2545.01)
M1_Encoder_A: CN5.B16 TP6.1 U5.97 | length 2637.6
  Top Layer w5: U5.97@1524.99,1845.61 1554.41,1845.59 1614.99,1785.01 1859.99,1785.01 1884.99,1760.01 1884.99,1280.01 1854.99,1250.01 TP6.1@1854.99,1220.01 1854.99,1120.01 v1(1859.99,1115.01) ; v1(2794.99,1115.01) 2819.99,1140.01 3213.89,1140.01 3254.99,1181.11 CN5.B16@3336.8,1181.11
  Bottom Layer w5: v1(1859.99,1115.01) 2009.99,1115.01 2044.99,1150.01 2182.43,1150.01 2277.12,1055.32 2735.3,1055.32 v1(2794.99,1115.01)
M1_Encoder_B: CN5.B17 TP19.1 U5.15 | length 3476.8
  Top Layer w5: U5.15@1248.61,2389.7 1248.61,2422.41 1249.36,2423.16 1249.36,2435.6 1254.99,2441.23 v1(1254.99,2450.01) ; v1(2229.87,2547.51) 2229.87,2525.13 2374.99,2380.01 2374.99,1278.79 2533.77,1120.01 TP19.1@2549.99,1120.01 2577.19,1120.01 2592.19,1105.01 2744.99,1105.01 2794.99,1155.01 3179.52,1155.01 3244.99,1220.48 CN5.B17@3322.83,1220.48
  Bottom Layer w5: v1(1254.99,2450.01) 1279.68,2474.7 1288.46,2474.7 1308.77,2495.01 1399.87,2495.01 1454.87,2550.01 2227.37,2550.01 v1(2229.87,2547.51)
M1_Encoder_Z: CN5.B18 TP39.1 U5.16 | length 3584.4
  Top Layer w5: U5.16@1232.86,2389.7 1232.86,2440.32 1237.49,2444.95 1237.49,2465.01 v1(1252.49,2480.01) ; v1(2359.99,2550.01) 2359.99,2524.57 2434.99,2449.57 2434.99,1809.58 2479.99,1764.58 2479.99,1285.01 2484.87,1280.13 2484.87,1195.13 2529.99,1150.01 2584.99,1150.01 2589.99,1145.01 TP39.1@2684.99,1145.01 2734.99,1145.01 2769.99,1180.01 3155.15,1180.01 3234.99,1259.85 CN5.B18@3336.8,1259.85
  Bottom Layer w5: v1(1252.49,2480.01) 1254.99,2482.51 1254.99,2499.76 1272.74,2517.51 1401.15,2517.51 1448.65,2565.01 2344.99,2565.01 v1(2359.99,2550.01)
M1_Hall_H1: CN5.A18 TP14.1 U5.1 | length 3080.1
  Top Layer w5: U5.1@1469.08,2389.7 1469.08,2421.72 v1(1499.87,2452.51) ; v1(2334.87,2449.7) 2334.87,2445.13 2389.99,2390.01 2389.99,1380.01 TP14.1@2409.99,1360.01 2419.99,1350.01 2419.99,1260.01 v1(2435.09,1244.91)
  Bottom Layer w5: v1(1499.87,2452.51) 1502.06,2454.7 2329.87,2454.7 v1(2334.87,2449.7) ; v1(2435.09,1244.91) 2449.99,1230.01 3149.99,1230.01 3179.83,1259.85 CN5.A18@3336.8,1259.85
M1_Hall_H2: CN5.A19 TP16.1 U5.2 | length 3125.1
  Top Layer w5: U5.2@1453.34,2389.7 1453.33,2429.57 1469.87,2446.11 1469.87,2449.57 v1(1469.99,2449.69) ; v1(2364.87,2449.7) 2364.87,2445.13 2404.99,2405.01 2404.99,1530.01 TP16.1@2434.99,1500.01 2439.99,1495.01 2439.99,1269.82 v1(2439.87,1269.7)
  Bottom Layer w5: v1(1469.99,2449.69) 1469.99,2454.82 1485.18,2470.01 2344.56,2470.01 v1(2364.87,2449.7) ; v1(2439.87,1269.7) 2439.87,1265.13 2459.99,1245.01 3129.99,1245.01 3184.2,1299.22 CN5.A19@3336.8,1299.22
M1_Hall_H3: CN5.B19 TP17.1 U5.3 | length 3146.4
  Top Layer w5: U5.3@1437.59,2389.7 1437.59,2435.05 1444.99,2442.45 v1(1444.99,2450.01) ; v1(2394.87,2449.7) 2419.87,2424.7 2419.87,2411.35 2419.99,2411.23 2419.99,1740.01 TP17.1@2439.99,1720.01 2439.99,1544.57 2464.99,1519.57 v1(2464.99,1270.01) ; v1(3087.49,1292.51) 3094.2,1299.22 CN5.B19@3336.8,1299.22
  Bottom Layer w5: v1(1444.99,2450.01) 1444.99,2455.25 1474.75,2485.01 2359.56,2485.01 v1(2394.87,2449.7) ; v1(2464.99,1270.01) 2474.99,1260.01 3054.99,1260.01 v1(3087.49,1292.51)
M1_Master_EN: CN5.A16 TP11.1 U5.105 | length 2745.7
  Top Layer w5: U5.105@1524.99,1971.59 1575.34,1971.58 1575.59,1971.83 1601.62,1971.83 1604.87,1968.58 1604.96,1968.58 1643.53,1930.01 1988.77,1930.01 2044.99,1873.79 2044.99,1395.01 2084.99,1355.01 2084.99,1195.01 TP11.1@2109.99,1170.01 2149.99,1130.01 2149.99,1049.82 v1(2144.87,1044.7)
  Bottom Layer w5: v1(2144.87,1044.7) 2219.56,970.01 2444.99,970.01 2464.99,990.01 2844.99,990.01 3014.99,1160.01 3229.99,1160.01 3251.09,1181.11 CN5.A16@3336.8,1181.11
M1_PWM_UH: CN5.A13 TP33.1 U5.80 | length 2955.7
  Top Layer w5: U5.80@1217.12,1789.7 1217.11,1699.11 1234.99,1681.23 1234.99,1561.23 1274.99,1521.23 1274.99,1439.25 1329.87,1384.37 1329.87,1230.69 1396.87,1163.69 1396.87,1042.7 v1(1414.87,1024.7) ; v1(2679.99,909.7) TP33.1@2679.99,950
  Bottom Layer w5: v1(1414.87,1024.7) 1441.96,1024.7 1484.84,1067.51 1559.68,1067.51 1592.18,1035.01 2083.23,1035.01 2193.54,924.7 2589.87,924.7 2604.87,909.7 v1(2679.99,909.7) 2914.68,909.7 3067.98,1063 CN5.A13@3336.8,1063
M1_PWM_UL: CN5.B13 TP7.1 U5.100 | length 2577.4
  Top Layer w5: U5.100@1524.99,1892.85 1574.6,1892.84 1597.43,1870.01 1934.99,1870.01 1979.99,1825.01 TP7.1@1979.99,1220.01 1979.99,1175.01 2040.3,1114.7 v1(2044.87,1114.7) ; v1(2839.99,1063) CN5.B13@3336.8,1063
  Bottom Layer w5: v1(2044.87,1114.7) 2064.87,1134.7 2176.52,1134.7 2270.9,1040.32 2770.74,1040.32 2777.62,1047.2 2792.12,1047.2 2799,1040.32 2817.31,1040.32 v1(2839.99,1063)
M1_PWM_VH: CN5.A14 TP22.1 U5.81 | length 2931.1
  Top Layer w5: U5.81@1232.86,1789.7 1232.86,1704.58 1249.99,1687.45 1249.99,1567.45 1289.99,1527.45 1289.99,1445.47 1346.87,1388.59 1346.87,1235.69 1414.99,1167.57 v1(1414.99,1052.51) ; v1(2547.37,947.2) 2554.99,954.82 TP22.1@2554.99,1000.01
  Bottom Layer w5: v1(1414.99,1052.51) 1417.49,1050.01 1445.94,1050.01 1457.82,1061.76 1478.62,1082.51 1565.9,1082.51 1598.4,1050.01 2089.45,1050.01 2199.45,940.01 2540.18,940.01 v1(2547.37,947.2) 2882.18,947.2 3037.35,1102.37 CN5.A14@3336.8,1102.37
M1_PWM_VL: CN5.B14 TP8.1 U5.101 | length 2591
  Top Layer w5: U5.101@1524.99,1908.6 1580.08,1908.58 1603.65,1885.01 1945,1885.01 2009.87,1820.14 2009.87,1350.13 TP8.1@2029.99,1330.01 2029.99,1164.58 v1(2079.87,1114.7) ; v1(2784.87,1029.7) 2784.87,1044.89 2842.35,1102.37 CN5.B14@3336.8,1102.37
  Bottom Layer w5: v1(2079.87,1114.7) 2084.56,1110.01 2177,1110.01 2262,1025.01 2780.18,1025.01 v1(2784.87,1029.7)
M1_PWM_WH: CN5.A15 TP5.1 U5.87 | length 2694.6
  Top Layer w5: U5.87@1327.35,1789.7 1327.35,1737.65 1339.99,1725.01 1339.99,1604.77 1379.99,1564.77 1379.99,1483.23 1464.99,1398.23 1464.99,1279.83 1549.99,1194.83 TP5.1@1549.99,1170.01 1584.99,1135.01 1584.99,1088.18 v1(1586.73,1086.44)
  Bottom Layer w5: v1(1586.73,1086.44) 1586.73,1082.9 1604.62,1065.01 2095.67,1065.01 2205.67,955.01 2454.99,955.01 2469.99,970.01 2859.99,970.01 3031.72,1141.74 CN5.A15@3336.8,1141.74
M1_PWM_WL: CN5.B15 TP15.1 U5.102 | length 2658.1
  Top Layer w5: U5.102@1524.99,1924.35 1585.46,1924.33 1586.21,1923.58 1586.3,1923.58 1609.87,1900.01 1969.99,1900.01 v1(2012.49,1857.51) ; v1(2322.49,1939.7) 2319.99,1937.2 2319.99,1310 2409.99,1220 2409.99,1175.01 TP15.1@2414.99,1170.01 2509.99,1075.01 2779.99,1075.01 2824.99,1120.01 3223.26,1120.01 3244.99,1141.74 CN5.B15@3336.8,1141.74
  Bottom Layer w5: v1(2012.49,1857.51) 2094.68,1939.7 v1(2322.49,1939.7)
M1_Res.Ex: CN5.B28 SB61.1 TP40.1 U5.33 | length 5557.2
  Top Layer w5: SB61.1@219.87,2415.01 279.56,2415.01 v1(279.87,2414.7) 320.18,2455.01 774.99,2455.01 896.22,2333.78 U5.33@924.99,2333.79 ; v1(2689.99,1195.01) 2684.99,1200.01 TP40.1@2684.99,1350.01 2799.68,1464.7 2929.87,1464.7 3118.72,1653.55 CN5.B28@3336.8,1653.55
  Bottom Layer w5: v1(279.87,2414.7) 274.87,2409.7 274.87,2034.7 262.99,2022.82 262.99,1746.46 309.87,1699.58 309.87,1252.7 527.56,1035.01 1346.09,1035.01 1396.09,1085.01 1434.87,1085.01 1469.56,1119.7 1839.88,1119.7 1855.19,1135.01 2008.77,1135.01 2038.77,1165.01 2189.99,1165.01 2284.68,1070.32 2645.5,1070.32 2689.99,1114.81 v1(2689.99,1195.01)
M1_Resolver_Cos: C10.2 R8.2 R95.2 U5.29 | length 466.7
  Top Layer w5: R95.2@649.87,2551.98 694.37,2551.98 ; 694.38,2551.97 R8.2@715.66,2551.97 715.82,2552.13 767.86,2552.13 869.98,2450.01 1003.77,2450.01 1028.14,2425.64 U5.29@1028.14,2389.7
M1_Resolver_Cos_C: CN5.B30 SB23.1 | length 6127.2
  Top Layer w5: v1(659.87,3119.7) 659.87,2819.7 704.87,2774.7 749.87,2774.7 774.83,2749.74 SB23.1@774.83,2719.38 ; v1(2624.87,1174.7) 2624.87,1194.7 2634.87,1204.7 2634.87,1414.7 2774.87,1554.7 2774.87,1639.7 2867.46,1732.29 CN5.B30@3336.8,1732.29
  Bottom Layer w5: v1(659.87,3119.7) 554.87,3119.7 354.87,2919.7 354.87,2274.7 329.87,2249.7 329.87,2019.7 306.87,1996.7 306.87,1771.7 394.87,1683.7 394.87,1250.7 570.87,1074.7 1323.66,1074.7 1387.66,1138.7 1428.87,1138.7 1465.18,1175.01 1951.33,1175.01 1976.02,1199.7 2254.87,1199.7 2329.87,1124.7 2584.87,1124.7 2624.87,1164.7 v1(2624.87,1174.7)
M1_Resolver_Sin: C13.2 R71.2 R94.2 U5.28 | length 429.9
  Top Layer w5: C13.2@820.66,2552.12 820.66,2529.34 v1(830.09,2519.91) 884.99,2465.01 1009.99,2465.01 1043.89,2431.11 U5.28@1043.89,2389.7
  Bottom Layer w5: R94.2@764.87,2561.98 765.18,2562.29 R71.2@819.99,2562.29 819.99,2530.01 v1(830.09,2519.91)
M1_Resolver_Sin_C: CN5.B29 SB4.1 | length 5284.1
  Top Layer w5: v1(334.87,2719.7) SB4.1@539.99,2719.7 ; v1(2649.87,1184.7) 2649.87,1404.69 2794.87,1549.69 2794.87,1629.69 2858.1,1692.92 CN5.B29@3336.8,1692.92
  Bottom Layer w5: v1(334.87,2719.7) 339.87,2714.7 339.87,2284.7 314.87,2259.7 314.87,2029.7 291.87,2006.7 291.87,1765.48 379.87,1677.48 379.87,1244.48 564.65,1059.7 1329.88,1059.7 1393.88,1123.7 1435.09,1123.7 1471.4,1160.01 1957.55,1160.01 1982.24,1184.7 2248.65,1184.7 2323.65,1109.7 2594.88,1109.7 2649.87,1164.69 v1(2649.87,1184.7)
M1_SHUNT1+: CN5.A21 SB11.1 SB21.1 | length 2923.6
  Top Layer w5: SB11.1@670.32,1565 726.52,1565 SB21.1@736.53,1555 v1(736.52,1489.7)
  Bottom Layer w5: v1(736.52,1489.7) 736.52,1473.04 889.86,1319.7 1229.88,1319.7 1371.69,1461.51 1443.68,1461.51 1460.74,1478.57 3021.43,1478.57 3122.04,1377.96 CN5.A21@3336.8,1377.96
M1_SHUNT1-: C7.1 CN5.B21 R7.1 | length 3087
  Top Layer w5: C7.1@619.87,1707.42 644.44,1707.42 660.78,1691.08 660.78,1687.34 676.13,1671.99 R7.1@679.87,1671.99 679.87,1659.7 v1(689.87,1649.7) ; v1(3039.87,1389.7) 3051.6,1377.97 CN5.B21@3336.8,1377.96
  Bottom Layer w5: v1(689.87,1649.7) 714.87,1624.7 714.87,1464.69 899.86,1279.7 1266.1,1279.7 1402.91,1416.51 1462.34,1416.51 1479.4,1433.57 2949.19,1433.57 2996.72,1386.04 3023.66,1386.04 3027.32,1389.7 v1(3039.87,1389.7)
M1_SHUNT2+: CN5.A22 SB31.1 SB32.1 | length 2596.5
  Top Layer w5: v1(939.99,1381.7) SB31.1@979.71,1381.7 979.71,1309.97 SB32.1@979.99,1309.69
  Bottom Layer w5: v1(939.99,1381.7) 951.99,1369.7 1134.87,1369.7 1164.87,1399.7 1274.87,1399.7 1287.3,1399.69 1364.12,1476.51 1437.46,1476.51 1454.52,1493.57 3040.99,1493.57 3117.23,1417.33 CN5.A22@3336.8,1417.33
M1_SHUNT2-: C22.1 CN5.B22 R24.1 | length 2462.4
  Top Layer w5: C22.1@1039.87,1211.99 1087.16,1211.99 1104.87,1229.7 v1(1104.87,1299.7) ; v1(3040.19,1417.33) CN5.B22@3336.8,1417.33
  Bottom Layer w5: v1(1104.87,1299.7) 1264.88,1299.7 1396.69,1431.51 1456.12,1431.51 1473.18,1448.57 2955.41,1448.57 3002.94,1401.04 3017.44,1401.04 3021.1,1404.7 3027.56,1404.7 v1(3040.19,1417.33)
M1_SHUNT3+: CN5.A23 SB37.1 SB38.1 | length 2484.6
  Top Layer w5: v1(1109.87,1389.7) 1118.19,1381.38 SB37.1@1149.83,1381.38 ; SB37.1@1149.83,1381.38 1149.83,1309.86 SB38.1@1149.99,1309.7 1149.99,1381.22 SB37.1@1149.83,1381.38
  Bottom Layer w5: v1(1109.87,1389.7) 1118.31,1389.7 1143.31,1414.7 1281.09,1414.7 1360.09,1493.7 1433.43,1493.7 1448.3,1508.57 3050.99,1508.57 3102.86,1456.7 CN5.A23@3336.8,1456.7
M1_SHUNT3-: C26.1 CN5.B23 R37.1 | length 2347.4
  Top Layer w5: C26.1@1199.87,1206.99 1261.15,1206.99 1279.87,1225.71 1279.87,1339.7 v1(1284.87,1344.7) ; v1(3010.19,1418.54) 3048.35,1456.7 CN5.B23@3336.8,1456.7
  Bottom Layer w5: v1(1284.87,1344.7) 1284.87,1349.7 1381.68,1446.51 1449.9,1446.51 1466.96,1463.57 2965.16,1463.57 v1(3010.19,1418.54)
M1_TEMP_ID: C9.2 R10.2 U5.61 | length 228.8
  Top Layer w5: C9.2@772.54,1790.01 832.47,1790.01 R10.2@834.87,1792.41 834.87,1812.69 862.84,1840.66 862.84,1877.98 877.7,1892.84 U5.61@924.99,1892.85
M1_TEMP_ID_C: CN5.A28 R10.1 | length 2904.1
  Top Layer w5: R10.1@834.87,1756.98 834.87,1737.63 v1(863.83,1708.67) ; v1(1724.87,1584.7) 1724.87,1624.89 v1(1799.99,1700.01)
  Bottom Layer w5: v1(863.83,1708.67) 844.99,1689.83 844.99,1575.01 984.99,1435.01 1114.99,1435.01 1234.99,1555.01 1695.18,1555.01 v1(1724.87,1584.7) ; v1(1799.99,1700.01) 1839.99,1660.01 3218.53,1660.01 3224.99,1653.55 CN5.A28@3336.8,1653.55
M1_Timer_ETR: CN5.A17 TP13.1 U5.27 | length 5572.6
  Top Layer w5: v1(277.37,2457.2) 295.18,2475.01 779.99,2475.01 899.99,2355.01 959.99,2355.01 972.49,2342.51 972.49,2322.52 985,2310.01 1025.19,2310.01 1059.63,2344.45 U5.27@1059.64,2389.7 ; v1(2329.99,989.7) TP13.1@2329.99,1070.01
  Bottom Layer w5: v1(277.37,2457.2) 259.87,2439.7 259.87,2040.92 247.99,2029.04 247.99,1740.24 294.87,1693.36 294.87,1241.69 516.55,1020.01 1352.31,1020.01 1402.31,1070.01 1441.09,1070.01 1475.78,1104.7 1595.3,1104.7 1619.99,1080.01 2134.31,1080.01 2224.62,989.7 v1(2329.99,989.7) 2334.68,985.01 2435.18,985.01 2460.18,1010.01 2819.99,1010.01 3004.99,1195.01 3219.99,1195.01 3245.46,1220.48 CN5.A17@3336.8,1220.48
M1_VBUS: C16.2 R14.2 U5.67 | length 248
  Top Layer w5: R14.2@844.99,1677.73 885.15,1677.73 C16.2@894.99,1687.57 899.91,1687.57 917.82,1705.48 917.82,1720.4 927.43,1730.01 996.21,1730.01 1012.39,1746.19 U5.67@1012.39,1789.7
M1_VBUS_C: CN5.A29 R14.1 | length 2752.1
  Top Layer w5: R14.1@844.99,1642.3 844.99,1620.01 v1(894.99,1570.01) ; v1(1684.87,1584.7) 1699.87,1599.7 1699.87,1649.89 v1(1784.99,1735.01)
  Bottom Layer w5: v1(894.99,1570.01) 1004.99,1460.01 1099.99,1460.01 1212.39,1572.41 1672.58,1572.41 v1(1684.87,1584.7) ; v1(1784.99,1735.01) 1799.55,1735.01 1854.86,1679.7 3199.87,1679.7 3213.09,1692.92 CN5.A29@3336.8,1692.92
M1_VOL+_U: SB76.2 SB77.2 U5.72 | length 377.8
  Top Layer w5: U5.72@1091.13,1789.7 1091.13,1825.96 v1(1114.87,1849.7)
  Bottom Layer w5: v1(1114.87,1849.7) 1164.87,1899.7 1164.87,1999.88 1210.74,2045.75 SB76.2@1227.91,2045.75 SB77.2@1227.91,2100.75
M1_VOL+_U_C: CN5.A25 R66.1 | length 2273.2
  Bottom Layer w5: R66.1@1274.87,1906.99 1274.87,1834.7 1419.56,1690.01 1754.99,1690.01 1825.3,1619.7 2949.86,1619.7 3014.55,1555.01 3170.42,1555.01 3189.99,1535.44 CN5.A25@3336.8,1535.44 CN5.A25@3351.8,1535.44
M1_VOL+_V: SB73.2 SB75.2 U5.58 | length 614.9
  Top Layer w5: U5.58@924.99,1940.09 975.06,1940.08 1004.99,1970.01 1004.99,2035.01 1049.99,2080.01 1094.99,2080.01 1125,2050 v1(1333.18,2050)
  Bottom Layer w5: v1(1333.18,2050) SB75.2@1372.43,2050 1376.37,2050 SB73.2@1376.37,2105
M1_VOL+_V_C: CN5.A26 R62.1 | length 2209.7
  Bottom Layer w5: R62.1@1419.87,1906.99 1416.13,1906.99 1400.78,1891.64 1400.78,1887.9 1382.27,1869.39 1382.27,1762.29 1434.77,1709.79 1764.77,1709.79 1834.86,1639.7 2954.86,1639.7 2999.55,1595.01 3184.79,1595.01 3204.99,1574.81 CN5.A26@3336.8,1574.81 CN5.A26@3351.8,1574.81
M1_VOL+_W: SB80.2 SB81.2 U5.75 | length 398.5
  Top Layer w5: v1(1047.49,2040.01) 1064.99,2040.01 1138.37,1966.63 U5.75@1138.38,1789.7
  Bottom Layer w5: v1(1047.49,2040.01) 1048.23,2040.75 SB81.2@1087.12,2040.75 1087.12,2100.94 SB80.2@1087.24,2101.06
M1_VOL+_W_C: CN5.A27 R68.1 | length 2474.9
  Top Layer w5: v1(2819.87,1599.7) 2840.18,1620.01 v1(3029.99,1620.01)
  Bottom Layer w5: R68.1@1119.87,1906.99 1119.87,1889.69 1087.27,1857.09 1087.27,1802.3 1219.87,1669.7 1744.86,1669.7 1814.86,1599.7 v1(2819.87,1599.7) ; v1(3029.99,1620.01) 3044.99,1635.01 3189.16,1635.01 3209.99,1614.18 CN5.A27@3336.8,1614.18
M2_Emergency(BKIN2): CN5.B37 SB40.2 | length 2847.1
  Top Layer w5: SB40.2@1434.99,1636.39 1449.99,1621.39 1449.99,1540.01 1519.99,1470.01 1519.99,1304.34 v1(1533.5,1290.83) ; v1(2584.87,1334.7) 2584.87,1844.89 2629.87,1889.89 2629.87,1994.88 2642.87,2007.88 CN5.B37@3336.8,2007.88
  Bottom Layer w5: v1(1533.5,1290.83) 1539.87,1297.2 2398.59,1297.2 2406.09,1304.7 2554.87,1304.7 v1(2584.87,1334.7)
M2_Emergency(BKIN): CN5.A37 SB69.2 | length 1726.2
  Bottom Layer w5: SB69.2@1706.92,1840.33 1722.24,1825.01 1930.19,1825.01 2130.19,2025.01 3219.99,2025.01 3237.12,2007.88 CN5.A37@3336.8,2007.88
M2_Enable1: CN5.B79 SB41.2 | length 2956.2
  Top Layer w5: SB41.2@1464.99,2583.63 1464.99,2929.82 v1(1479.87,2944.7) ; v1(2689.99,2790.01) 2794.99,2790.01 3009.99,3005.01 3009.99,3234.7 3046.17,3270.88 3046.17,3565.19 3142.4,3661.42 CN5.B79@3336.8,3661.43
  Bottom Layer w5: v1(1479.87,2944.7) 1539.87,2944.7 1694.56,2790.01 v1(2689.99,2790.01)
M2_Enable2: CN5.B80 SB29.2 | length 3746.9
  Top Layer w5: v1(824.87,3014.7) 854.87,3014.7 909.87,2959.7 909.87,2799.71 869.87,2759.71 SB29.2@869.87,2593.32 ; v1(2988.1,3016.9) 2989.99,3018.79 2989.99,3249.7 3027.67,3287.38 3027.67,3578.69 3149.77,3700.79 CN5.B80@3336.8,3700.8
  Bottom Layer w5: v1(824.87,3014.7) 1562.3,3014.7 1717.3,2859.7 2874.86,2859.7 2988.1,2972.94 v1(2988.1,3016.9)
M2_Encoder_A: CN5.B41 SB52.2 | length 1728.1
  Top Layer w5: SB52.2@1708.61,2070.01 1708.73,2070.13 v1(1749.23,2070.13) ; v1(3047.49,2162.51) 3064.99,2145.01 3129.99,2145.01 3150.34,2165.36 CN5.B41@3336.8,2165.36
  Bottom Layer w5: v1(1749.23,2070.13) 1784.35,2035.01 1900.18,2035.01 1909.87,2044.7 1909.87,2073.47 1951.1,2114.7 1984.87,2114.7 2032.68,2162.51 v1(3047.49,2162.51)
M2_Encoder_B: CN5.B42 SB66.2 | length 1521.4
  Top Layer w5: v1(3104.99,2185.01) 3124.71,2204.73 CN5.B42@3336.8,2204.74
  Bottom Layer w5: SB66.2@1871.33,2069.68 1884.86,2069.68 1944.88,2129.7 1974.87,2129.7 2025.18,2180.01 3083.77,2180.01 3084.12,2180.36 3100.34,2180.36 v1(3104.99,2185.01)
M2_Encoder_Z: CN5.B43 SB71.2 | length 1707.3
  Top Layer w5: v1(3099.99,2230.01) 3104.99,2230.01 3119.08,2244.1 CN5.B43@3336.8,2244.11
  Bottom Layer w5: SB71.2@1703.61,2160.01 1703.61,2162.51 1742.49,2162.51 1769.99,2190.01 1909.56,2190.01 1939.87,2159.7 1957.12,2159.7 2017.43,2220.01 2289.56,2220.01 2304.87,2204.7 2574.56,2204.7 2599.87,2230.01 v1(3099.99,2230.01)
M2_Hall_H1: CN5.A43 SB47.2 | length 1674.2
  Top Layer w5: SB47.2@1702.11,2240 1729.98,2240 1754.99,2265.01 1909.99,2265.01 v1(1929.99,2245.01)
  Bottom Layer w5: v1(1929.99,2245.01) 1963.96,2245.01 1988.65,2269.7 2519.86,2269.7 2529.86,2259.7 3114.88,2259.7 3130.47,2244.11 CN5.A43@3336.8,2244.11
M2_Hall_H2: CN5.A44 SB45.2 | length 4080.8
  Top Layer w5: SB45.2@1544.99,1636.38 1544.99,1630.01 1582.7,1592.3 1582.7,1389.49 1637.49,1334.7 v1(1637.49,1097.51) ; v1(2095.03,2287.2) 2097.68,2287.2 2239.99,2144.89 2239.99,2071.35 2289.99,2021.35 2289.99,1297.56 2367.8,1219.75 2367.8,1155.97 2439.99,1083.78 2439.99,1014.58 v1(2432.49,1007.08)
  Bottom Layer w5: v1(1637.49,1097.51) 1639.99,1095.01 2144.56,1095.01 2229.87,1009.7 2429.87,1009.7 v1(2432.49,1007.08) ; v1(2095.03,2287.2) 2095.18,2287.35 2537.23,2287.35 2541.11,2283.47 CN5.A44@3336.8,2283.48
M2_Hall_H3: CN5.B44 SB55.2 | length 1500.2
  Top Layer w5: SB55.2@1862.11,2325 1899.57,2325 v1(1909.87,2314.7) ; v1(3039.99,2310.01) 3066.53,2283.47 CN5.B44@3336.8,2283.48
  Bottom Layer w5: v1(1909.87,2314.7) 1968.65,2314.7 1973.65,2319.7 2164.87,2319.7 2169.87,2324.7 3025.3,2324.7 v1(3039.99,2310.01)
M2_PWM_UH: CN5.A38 SB84.2 | length 6348.4
  Top Layer w5: v1(200.09,1229.91) 146.99,1283.01 146.99,1792.01 269.99,1915.01 503.19,1915.01 531.09,1942.91 v1(531.09,1968.91) ; v1(1924.99,1850.01) 1954.99,1820.01 1954.99,1309.82 1934.87,1289.7 1934.87,1145.13 2084.99,995.01 2084.99,730.01 2004.99,650.01 v1(1944.99,650.01)
  Bottom Layer w5: v1(200.09,1229.91) 200.09,1079.91 249.99,1030.01 249.99,785.01 384.99,650.01 v1(1944.99,650.01) ; v1(531.09,1968.91) 537.25,1962.75 677.25,1962.75 708.93,1931.07 SB84.2@721.06,1931.07 ; v1(1924.99,1850.01) 2114.99,2040.01 3210.19,2040.01 3217.44,2047.26 CN5.A38@3336.8,2047.25
M2_PWM_UL: CN5.B38 SB8.2 | length 4793.9
  Top Layer w5: v1(374.87,1989.7) 379.12,1993.95 SB8.2@586.69,1993.95 ; v1(2544.87,1184.7) 2564.87,1204.7 2564.87,1846.11 2614.87,1896.11 2614.87,2012.13 2649.99,2047.25 CN5.B38@3336.8,2047.25
  Bottom Layer w5: v1(374.87,1989.7) 354.87,1969.7 354.87,1777.47 434.99,1697.35 434.99,1310.92 630.5,1115.41 1293.57,1115.41 1370.86,1192.7 1395.3,1192.7 1427.3,1224.7 1558.28,1224.7 1570.78,1237.2 2357.38,1237.2 2414.88,1179.7 2539.87,1179.7 v1(2544.87,1184.7)
M2_PWM_VH: CN5.A39 SB88.2 | length 3907.6
  Top Layer w5: v1(1899.99,1850.01) 1899.99,1825.01 1932.49,1792.51 v1(1932.49,1344.7)
  Bottom Layer w5: SB88.2@721.37,1866.07 654.99,1799.69 654.99,1449.01 859.49,1244.51 1283.27,1244.51 1383.46,1344.7 v1(1932.49,1344.7) ; v1(1899.99,1850.01) 1899.99,1859.81 2099.88,2059.7 3184.87,2059.7 3211.79,2086.62 CN5.A39@3336.8,2086.62
M2_PWM_VL: CN5.B39 SB6.2 | length 4687.1
  Top Layer w5: v1(374.87,1864.7) 390.18,1880.01 512.99,1880.01 547.99,1915.01 570.31,1915.01 SB6.2@586.37,1931.07 ; v1(2544.87,1209.7) 2549.87,1214.7 2549.87,1852.33 2599.87,1902.33 2599.87,2031.5 2654.99,2086.62 CN5.B39@3336.8,2086.62
  Bottom Layer w5: v1(374.87,1864.7) 374.87,1778.69 449.99,1703.57 449.99,1317.14 636.72,1130.41 1287.35,1130.41 1363.87,1206.93 1363.87,1227.71 1375.86,1239.7 1399.86,1239.7 1414.86,1254.7 1545.84,1254.7 1558.34,1267.2 2372.68,1267.2 2424.87,1215.01 2539.87,1215.01 2544.87,1210.01 v1(2544.87,1209.7)
M2_PWM_WH: CN5.A40 SB92.2 | length 4052.9
  Top Layer w5: v1(2344.87,1334.7) 2359.99,1349.82 2359.99,2064.58 v1(2344.87,2079.7)
  Bottom Layer w5: SB92.2@586.37,1866.54 639.99,1812.92 639.99,1440.23 850.71,1229.51 1289.49,1229.51 1387.18,1327.2 2337.37,1327.2 v1(2344.87,1334.7) ; v1(2344.87,2079.7) 2355.18,2090.01 3075.19,2090.01 3111.17,2125.99 CN5.A40@3336.8,2125.99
